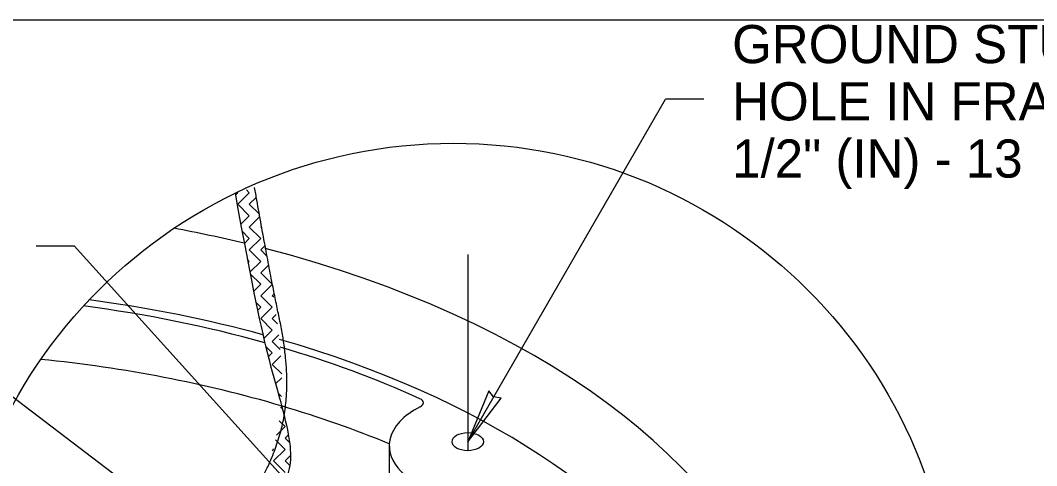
# Model space of a CAD drawing. Extents: x 99862 to 103151, y 100000 to 105076.
# Drawn here: x 101341.6 to 101767.6, y 104888.7 to 105075.5 of the extents above; entities that cross this region are included whole.
import ezdxf

# ---------------------------------------------------------------- set-up
doc = ezdxf.new("R2010")
doc.units = 0
for name, color, linetype in [('Level 1', 7, 'Continuous'), ('Level 11', 7, 'Continuous'), ('Level 15', 7, 'Continuous'), ('Level 16', 7, 'Continuous'), ('Level 20', 7, 'Continuous')]:
    doc.layers.add(name, color=color, linetype=linetype)

msp = doc.modelspace()

# ---------------------------------------------------------------- linework, layer by layer
at = {"layer": 'Level 1'}
msp.add_lwpolyline([(99862, 102999.5), (103151, 102999.5), (103151, 105075.5), (99862, 105075.5)], close=True, dxfattribs=at)
at = {"layer": 'Level 11'}
msp.add_line((101496.23, 104897.02), (101496.23, 104872.52), dxfattribs=at)
msp.add_line((101496.23, 104897.02), (101496.23, 104872.52), dxfattribs=at)
for centre, major_axis, start_param, end_param in [((101289.11, 104780.28), (-378.75, 0), 4.315801, 4.398691), ((101289.11, 104780.28), (-378.75, 0), 2.356194, 4.290429), ((101289.11, 104755.79), (360, 0), 1.128288, 1.342846), ((101289.11, 104755.79), (-355.12, 0), 4.260909, 4.488171), ((101289.11, 104755.79), (360, 0), 5.877634, 7.390205), ((101289.11, 104755.79), (-355.12, 0), 4.044341, 4.240741), ((101289.11, 104731.29), (-355.12, 0), 4.239667, 4.539527), ((101506.77, 104915.05), (-3.75, 0), 2.282895, 4.044341), ((101289.11, 104731.29), (-355.12, 0), 4.089614, 4.238763), ((101533.73, 104897.02), (-37.5, 0), 5.424488, 6.166441), ((101533.73, 104897.02), (-37.5, 0), 6.166441, 8.712679)]:
    msp.add_ellipse(centre, major_axis=major_axis, ratio=0.57735, start_param=start_param, end_param=end_param, dxfattribs=at)
msp.add_ellipse((101529.1, 104898.76), major_axis=(6.56, 0), ratio=0.57735, dxfattribs=at)
at = {"layer": 'Level 15'}
for p, q in [((101529.1, 104898.76), (101612.08, 105042.49)), ((101628.08, 105042.49), (101612.08, 105042.49)), ((101348.14, 104980.88), (101364.14, 104980.88)), ((101477.94, 104854.93), (101364.14, 104980.88)), ((101529.12, 104977.33), (101529.12, 104894.98)), ((101327.27, 104925.93), (101424.02, 104852.52))]:
    msp.add_line(p, q, dxfattribs=at)
msp.add_lwpolyline([(101529.1, 104898.76), (101543.1, 104917.04), (101539.98, 104917.62), (101537.93, 104920.03)], close=True, dxfattribs=at)
msp.add_circle((101523.08, 104813.74), 210.18, dxfattribs=at)
at = {"layer": 'Level 16'}
for p, q in [((101431.74, 105002.14), (101432.76, 105003.16)), ((101432.76, 105003.16), (101432.65, 105003.28)), ((101432.76, 104998.36), (101437.56, 105003.16)), ((101437.56, 105003.16), (101436.36, 105004.37)), ((101437.56, 104998.36), (101440.51, 105001.31)), ((101437.56, 104993.56), (101432.76, 104998.36)), ((101441.77, 104994.16), (101437.56, 104998.36)), ((101433.98, 104989.98), (101437.56, 104993.56)), ((101437.56, 104988.76), (101441.95, 104993.15)), ((101442.36, 104983.96), (101437.56, 104988.76)), ((101442.36, 104988.76), (101442.68, 104989.08)), ((101442.82, 104988.31), (101442.36, 104988.76)), ((101437.56, 104983.96), (101434.53, 104987)), ((101435.49, 104981.89), (101437.56, 104983.96)), ((101437.56, 104979.16), (101442.36, 104983.96)), ((101442.36, 104979.16), (101444.13, 104980.93)), ((101442.36, 104974.36), (101437.56, 104979.16)), ((101444.9, 104976.63), (101442.36, 104979.16)), ((101437.56, 104974.36), (101436.77, 104975.16)), ((101437.02, 104973.82), (101437.56, 104974.36)), ((101437.8, 104969.8), (101442.36, 104974.36)), ((101442.36, 104969.56), (101445.57, 104972.77)), ((101442.36, 104964.76), (101437.92, 104969.21)), ((101446.88, 104965.05), (101442.36, 104969.56)), ((101439.38, 104961.79), (101442.36, 104964.76)), ((101442.36, 104959.96), (101446.96, 104964.56)), ((101447.16, 104955.16), (101442.36, 104959.96)), ((101447.16, 104959.96), (101447.63, 104960.43)), ((101447.8, 104959.33), (101447.16, 104959.96)), ((101442.36, 104955.16), (101440.31, 104957.22)), ((101441.02, 104953.82), (101442.36, 104955.16)), ((101442.36, 104950.36), (101447.16, 104955.16)), ((101447.16, 104945.56), (101442.36, 104950.36)), ((101447.16, 104950.36), (101448.88, 104952.08)), ((101449.4, 104948.12), (101447.16, 104950.36)), ((101443.63, 104942.03), (101447.16, 104945.56)), ((101447.16, 104940.76), (101449.95, 104943.55)), ((101447.16, 104935.96), (101444.43, 104938.69)), ((101450.56, 104937.37), (101447.16, 104940.76)), ((101445.53, 104934.33), (101447.16, 104935.96)), ((101447.16, 104931.16), (101450.76, 104934.77)), ((101451.14, 104927.19), (101447.16, 104931.16)), ((101448.57, 104922.97), (101451.17, 104925.57)), ((101451.06, 104917.67), (101449.64, 104919.09)), ((101450.64, 104915.44), (101450.95, 104915.75)), ((101450.72, 104912.83), (101451.21, 104913.32)), ((101452.55, 104905.06), (101450.07, 104907.54)), ((101448.93, 104901.44), (101452.55, 104905.06)), ((101452.55, 104895.46), (101448.48, 104899.53)), ((101452.55, 104900.26), (101453.94, 104901.65)), ((101454.46, 104898.35), (101452.55, 104900.26)), ((101447.16, 104894.87), (101447.75, 104895.46)), ((101447.75, 104895.46), (101447.44, 104895.77)), ((101447.75, 104890.66), (101452.55, 104895.46)), ((101452.55, 104885.86), (101447.75, 104890.66)), ((101452.55, 104890.66), (101454.82, 104892.93)), ((101454.5, 104888.71), (101452.55, 104890.66))]:
    msp.add_line(p, q, dxfattribs=at)
for points, degree in [([(101435.6, 104871.52), (101448.4, 104890.22), (101455.35, 104925.79), (101445.22, 104973.98), (101439.8, 105005.37)], 2), ([(101431.59, 105002.96), (101439.09, 104961.95), (101445.49, 104931.66), (101457.17, 104895.06), (101452.46, 104879.14), (101438.67, 104863.3), (101430.96, 104847.87), (101428.6, 104833.33)], 3)]:
    msp.add_open_spline(points, degree=degree, dxfattribs=at)

# ---------------------------------------------------------------- texts
at = {"layer": 'Level 20'}
for s, p in [('GROUND STUD - THREAD INTO PREDRILLED ', (101639.96, 105057.52)), ('HOLE IN FRAME FLANGE, DRILL AND TAP ', (101639.96, 105033.52)), ('1/2" (IN) - 13', (101639.96, 105009.52))]:
    msp.add_text(s, height=16, dxfattribs=at).set_placement(p)

doc.saveas('drawing.dxf')
